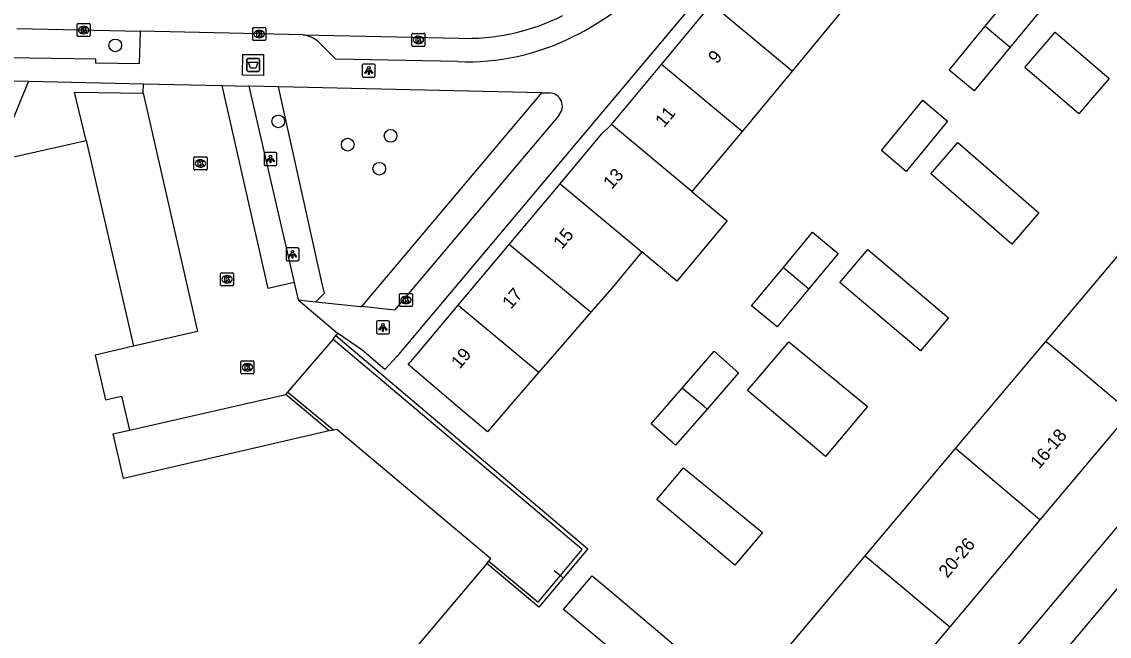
# Model space of a CAD drawing. Extents: x 162532 to 163264, y 381233 to 382042.
# Drawn here: x 162954.6 to 163038.2, y 381728.5 to 381775.7 of the extents above; entities that cross this region are included whole.
import ezdxf

# ---------------------------------------------------------------- set-up
doc = ezdxf.new("R2010")
doc.units = 0
for name, color, linetype in [('IMGEO_Afval_apart_plaats', 7, 'Continuous'), ('IMGEO_Boom', 7, 'Continuous'), ('IMGEO_Groenvoorziening', 7, 'Continuous'), ('IMGEO_Hek', 7, 'Continuous'), ('IMGEO_Kolk', 7, 'Continuous'), ('IMGEO_Lichtpunt', 7, 'Continuous'), ('IMGEO_Muur', 7, 'Continuous'), ('IMGEO_Pand', 7, 'Continuous'), ('IMGEO_Pand_nummerreeks', 7, 'Continuous'), ('IMGEO_Parkeervlak_open', 7, 'Continuous'), ('IMGEO_Rijbaan_lokaal_gesloten', 7, 'Continuous'), ('IMGEO_Rijbaan_lokaal_open', 7, 'Continuous'), ('IMGEO_Voetpad_gesloten', 7, 'Continuous'), ('IMGEO_Voetpad_open', 7, 'Continuous')]:
    doc.layers.add(name, color=color, linetype=linetype)

msp = doc.modelspace()

# ---------------------------------------------------------------- linework, layer by layer
at = {"layer": 'IMGEO_Afval_apart_plaats'}
for p, q in [((162971.93, 381771.991), (162971.93, 381772.791)), ((162971.93, 381772.791), (162971.93, 381771.991)), ((162972.03, 381772.891), (162972.82, 381772.891)), ((162972.82, 381772.891), (162972.03, 381772.891)), ((162972.92, 381772.791), (162972.92, 381771.991)), ((162972.92, 381771.991), (162972.92, 381772.791)), ((162972.82, 381771.891), (162972.03, 381771.891)), ((162972.03, 381771.891), (162972.82, 381771.891))]:
    msp.add_line(p, q, dxfattribs=at)
msp.add_lwpolyline([(162972.073, 381772.605), (162972.777, 381772.605), (162972.628, 381772.135), (162972.222, 381772.135), (162972.073, 381772.605)], dxfattribs=at)
for centre, start, end in [((162972.03, 381772.791), 90, 180), ((162972.03, 381772.791), 90, 180), ((162972.82, 381772.791), 0, 90), ((162972.82, 381772.791), 360, 90), ((162972.03, 381771.991), 180, 270), ((162972.03, 381771.991), 180, 270), ((162972.82, 381771.991), 270, 0), ((162972.82, 381771.991), 270, 0)]:
    msp.add_arc(centre, 0.1, start, end, dxfattribs=at)
at = {"layer": 'IMGEO_Boom'}
for centre in [(162961.829, 381773.885), (162974.352, 381768.05), (162982.984, 381766.94), (162979.697, 381766.265), (162982.114, 381764.415)]:
    msp.add_circle(centre, 0.489, dxfattribs=at)
at = {"layer": 'IMGEO_Groenvoorziening'}
for points in [[(162977.247, 381754.194), (162977.909, 381754.864), (162977.734, 381755.574), (162974.381, 381770.706)], [(162980.775, 381753.828), (162994.602, 381770.25)]]:
    msp.add_lwpolyline(points, dxfattribs=at)
at = {"layer": 'IMGEO_Hek'}
msp.add_lwpolyline([(162995.56, 381733.575), (162996.032, 381733.167)], dxfattribs=at)
at = {"layer": 'IMGEO_Kolk'}
for p, q in [((162958.909, 381774.634), (162958.909, 381775.486)), ((162958.984, 381775.56), (162959.836, 381775.56)), ((162959.397, 381775.34), (162959.422, 381775.34)), ((162959.91, 381775.486), (162959.91, 381774.634)), ((162972.391, 381774.327), (162972.391, 381775.179)), ((162972.466, 381775.253), (162973.318, 381775.253)), ((162973.392, 381775.179), (162973.392, 381774.327)), ((162959.836, 381774.56), (162958.984, 381774.56)), ((162959.42, 381774.78), (162959.395, 381774.78)), ((162972.902, 381774.473), (162972.877, 381774.473)), ((162972.879, 381775.033), (162972.904, 381775.033)), ((162984.621, 381773.886), (162984.621, 381774.738)), ((162984.696, 381774.812), (162985.548, 381774.812)), ((162985.109, 381774.592), (162985.134, 381774.592)), ((162985.622, 381774.738), (162985.622, 381773.886)), ((162973.318, 381774.253), (162972.466, 381774.253)), ((162985.548, 381773.812), (162984.696, 381773.812)), ((162985.132, 381774.032), (162985.107, 381774.032)), ((162967.881, 381764.392), (162967.881, 381765.244)), ((162967.956, 381765.318), (162968.808, 381765.318)), ((162968.882, 381765.244), (162968.882, 381764.392)), ((162968.808, 381764.318), (162967.956, 381764.318)), ((162968.392, 381764.538), (162968.367, 381764.538)), ((162968.369, 381765.098), (162968.394, 381765.098)), ((162969.921, 381755.504), (162969.921, 381756.356)), ((162969.996, 381756.43), (162970.848, 381756.43)), ((162970.409, 381756.21), (162970.434, 381756.21)), ((162970.922, 381756.356), (162970.922, 381755.504)), ((162970.848, 381755.43), (162969.996, 381755.43)), ((162970.432, 381755.65), (162970.407, 381755.65)), ((162983.664, 381753.912), (162983.664, 381754.764)), ((162983.739, 381754.838), (162984.591, 381754.838)), ((162984.152, 381754.618), (162984.177, 381754.618)), ((162984.665, 381754.764), (162984.665, 381753.912)), ((162984.591, 381753.838), (162983.739, 381753.838)), ((162984.175, 381754.058), (162984.15, 381754.058)), ((162971.489, 381748.736), (162971.489, 381749.588)), ((162971.564, 381749.662), (162972.416, 381749.662)), ((162971.977, 381749.442), (162972.002, 381749.442)), ((162972.49, 381749.588), (162972.49, 381748.736)), ((162972.416, 381748.662), (162971.564, 381748.662)), ((162972, 381748.882), (162971.975, 381748.882))]:
    msp.add_line(p, q, dxfattribs=at)
for points in [[(162958.909, 381774.634), (162958.909, 381775.486)], [(162958.984, 381775.56), (162959.836, 381775.56)], [(162959.23, 381775.26), (162959.353, 381775.26), (162959.353, 381775.109), (162959.483, 381775.26), (162959.647, 381775.26), (162959.501, 381775.109), (162959.654, 381774.86), (162959.502, 381774.86), (162959.417, 381775.024), (162959.353, 381774.957), (162959.353, 381774.86), (162959.23, 381774.86), (162959.23, 381775.26)], [(162959.91, 381775.486), (162959.91, 381774.634)], [(162972.391, 381774.327), (162972.391, 381775.179)], [(162972.466, 381775.253), (162973.318, 381775.253)], [(162973.392, 381775.179), (162973.392, 381774.327)], [(162959.836, 381774.56), (162958.984, 381774.56)], [(162972.712, 381774.953), (162972.835, 381774.953), (162972.835, 381774.802), (162972.965, 381774.953), (162973.129, 381774.953), (162972.983, 381774.802), (162973.136, 381774.553), (162972.984, 381774.553), (162972.899, 381774.717), (162972.835, 381774.65), (162972.835, 381774.553), (162972.712, 381774.553), (162972.712, 381774.953)], [(162984.621, 381773.886), (162984.621, 381774.738)], [(162984.696, 381774.812), (162985.548, 381774.812)], [(162984.942, 381774.512), (162985.065, 381774.512), (162985.065, 381774.361), (162985.195, 381774.512), (162985.359, 381774.512), (162985.213, 381774.361), (162985.366, 381774.112), (162985.214, 381774.112), (162985.129, 381774.276), (162985.065, 381774.209), (162985.065, 381774.112), (162984.942, 381774.112), (162984.942, 381774.512)], [(162985.622, 381774.738), (162985.622, 381773.886)], [(162973.318, 381774.253), (162972.466, 381774.253)], [(162985.548, 381773.812), (162984.696, 381773.812)], [(162967.881, 381764.392), (162967.881, 381765.244)], [(162967.956, 381765.318), (162968.808, 381765.318)], [(162968.882, 381765.244), (162968.882, 381764.392)], [(162968.808, 381764.318), (162967.956, 381764.318)], [(162968.202, 381765.018), (162968.325, 381765.018), (162968.325, 381764.867), (162968.455, 381765.018), (162968.619, 381765.018), (162968.473, 381764.867), (162968.626, 381764.618), (162968.474, 381764.618), (162968.389, 381764.782), (162968.325, 381764.715), (162968.325, 381764.618), (162968.202, 381764.618), (162968.202, 381765.018)], [(162969.921, 381755.504), (162969.921, 381756.356)], [(162969.996, 381756.43), (162970.848, 381756.43)], [(162970.242, 381756.13), (162970.365, 381756.13), (162970.365, 381755.979), (162970.495, 381756.13), (162970.659, 381756.13), (162970.513, 381755.979), (162970.666, 381755.73), (162970.514, 381755.73), (162970.429, 381755.894), (162970.365, 381755.827), (162970.365, 381755.73), (162970.242, 381755.73), (162970.242, 381756.13)], [(162970.922, 381756.356), (162970.922, 381755.504)], [(162970.848, 381755.43), (162969.996, 381755.43)], [(162983.664, 381753.912), (162983.664, 381754.764)], [(162983.739, 381754.838), (162984.591, 381754.838)], [(162983.985, 381754.538), (162984.108, 381754.538), (162984.108, 381754.387), (162984.238, 381754.538), (162984.402, 381754.538), (162984.256, 381754.387), (162984.409, 381754.138), (162984.257, 381754.138), (162984.172, 381754.302), (162984.108, 381754.235), (162984.108, 381754.138), (162983.985, 381754.138), (162983.985, 381754.538)], [(162984.665, 381754.764), (162984.665, 381753.912)], [(162984.591, 381753.838), (162983.739, 381753.838)], [(162971.489, 381748.736), (162971.489, 381749.588)], [(162971.564, 381749.662), (162972.416, 381749.662)], [(162971.81, 381749.362), (162971.933, 381749.362), (162971.933, 381749.211), (162972.063, 381749.362), (162972.227, 381749.362), (162972.081, 381749.211), (162972.234, 381748.962), (162972.082, 381748.962), (162971.997, 381749.126), (162971.933, 381749.059), (162971.933, 381748.962), (162971.81, 381748.962), (162971.81, 381749.362)], [(162972.49, 381749.588), (162972.49, 381748.736)], [(162972.416, 381748.662), (162971.564, 381748.662)]]:
    msp.add_lwpolyline(points, dxfattribs=at)
for centre, start, end in [((162958.986, 381775.484), 91.55205, 178.44795), ((162958.986, 381775.484), 91.55205, 178.44795), ((162959.834, 381775.484), 1.55205, 88.44795), ((162959.834, 381775.484), 1.55205, 88.44795), ((162972.468, 381775.177), 91.55205, 178.44795), ((162972.468, 381775.177), 91.55205, 178.44795), ((162973.316, 381775.177), 1.55205, 88.44795), ((162973.316, 381775.177), 1.55205, 88.44795), ((162958.986, 381774.636), 181.55205, 268.44795), ((162958.986, 381774.636), 181.55205, 268.44795), ((162959.834, 381774.636), 271.55205, 358.44795), ((162959.834, 381774.636), 271.55205, 358.44795), ((162972.468, 381774.329), 181.55205, 268.44795), ((162972.468, 381774.329), 181.55205, 268.44795), ((162973.316, 381774.329), 271.55205, 358.44795), ((162973.316, 381774.329), 271.55205, 358.44795), ((162984.698, 381774.736), 91.55205, 178.44795), ((162984.698, 381774.736), 91.55205, 178.44795), ((162985.546, 381774.736), 1.55205, 88.44795), ((162985.546, 381774.736), 1.55205, 88.44795), ((162984.698, 381773.888), 181.55205, 268.44795), ((162984.698, 381773.888), 181.55205, 268.44795), ((162985.546, 381773.888), 271.55205, 358.44795), ((162985.546, 381773.888), 271.55205, 358.44795), ((162967.958, 381765.242), 91.55205, 178.44795), ((162967.958, 381765.242), 91.55205, 178.44795), ((162968.806, 381765.242), 1.55205, 88.44795), ((162968.806, 381765.242), 1.55205, 88.44795), ((162967.958, 381764.394), 181.55205, 268.44795), ((162967.958, 381764.394), 181.55205, 268.44795), ((162968.806, 381764.394), 271.55205, 358.44795), ((162968.806, 381764.394), 271.55205, 358.44795), ((162969.998, 381756.354), 91.55205, 178.44795), ((162969.998, 381756.354), 91.55205, 178.44795), ((162970.846, 381756.354), 1.55205, 88.44795), ((162970.846, 381756.354), 1.55205, 88.44795), ((162969.998, 381755.506), 181.55205, 268.44795), ((162969.998, 381755.506), 181.55205, 268.44795), ((162970.846, 381755.506), 271.55205, 358.44795), ((162970.846, 381755.506), 271.55205, 358.44795), ((162983.741, 381754.762), 91.55205, 178.44795), ((162983.741, 381754.762), 91.55205, 178.44795), ((162984.589, 381754.762), 1.55205, 88.44795), ((162984.589, 381754.762), 1.55205, 88.44795), ((162983.741, 381753.914), 181.55205, 268.44795), ((162983.741, 381753.914), 181.55205, 268.44795), ((162984.589, 381753.914), 271.55205, 358.44795), ((162984.589, 381753.914), 271.55205, 358.44795), ((162971.566, 381749.586), 91.55205, 178.44795), ((162971.566, 381749.586), 91.55205, 178.44795), ((162972.414, 381749.586), 1.55205, 88.44795), ((162972.414, 381749.586), 1.55205, 88.44795), ((162971.566, 381748.738), 181.55205, 268.44795), ((162971.566, 381748.738), 181.55205, 268.44795), ((162972.414, 381748.738), 271.55205, 358.44795), ((162972.414, 381748.738), 271.55205, 358.44795)]:
    msp.add_arc(centre, 0.0765, start, end, dxfattribs=at)
for centre, major_axis, ratio, start_param, end_param in [((162959.396, 381775.06), (-0.387, 0.002), 0.722429, 4.712389, 7.853982), ((162959.421, 381775.06), (-0.39, 0.002), 0.717154, 1.570796, 4.712389), ((162972.878, 381774.753), (-0.387, 0.002), 0.722429, 4.712389, 7.853982), ((162972.903, 381774.753), (-0.39, 0.002), 0.717154, 1.570796, 4.712389), ((162985.108, 381774.312), (-0.387, 0.002), 0.722429, 4.712389, 7.853982), ((162985.133, 381774.312), (-0.39, 0.002), 0.717154, 1.570796, 4.712389), ((162968.368, 381764.818), (-0.387, 0.002), 0.722429, 4.712389, 7.853982), ((162968.393, 381764.818), (-0.39, 0.002), 0.717154, 1.570796, 4.712389), ((162970.408, 381755.93), (-0.387, 0.002), 0.722429, 4.712389, 7.853982), ((162970.433, 381755.93), (-0.39, 0.002), 0.717154, 1.570796, 4.712389), ((162984.151, 381754.338), (-0.387, 0.002), 0.722429, 4.712389, 7.853982), ((162984.176, 381754.338), (-0.39, 0.002), 0.717154, 1.570796, 4.712389), ((162971.976, 381749.162), (-0.387, 0.002), 0.722429, 4.712389, 7.853982), ((162972.001, 381749.162), (-0.39, 0.002), 0.717154, 1.570796, 4.712389)]:
    msp.add_ellipse(centre, major_axis=major_axis, ratio=ratio, start_param=start_param, end_param=end_param, dxfattribs=at)
at = {"layer": 'IMGEO_Lichtpunt'}
for p, q in [((162980.81, 381772.359), (162980.81, 381771.552)), ((162980.81, 381772.359), (162980.81, 381771.552)), ((162981.712, 381772.454), (162980.904, 381772.454)), ((162981.712, 381772.454), (162980.904, 381772.454)), ((162981.806, 381771.552), (162981.806, 381772.359)), ((162981.806, 381771.552), (162981.806, 381772.359)), ((162980.904, 381771.458), (162981.712, 381771.458)), ((162980.904, 381771.458), (162981.712, 381771.458)), ((162973.262, 381765.571), (162973.262, 381764.764)), ((162973.262, 381765.571), (162973.262, 381764.764)), ((162974.164, 381765.666), (162973.356, 381765.666)), ((162974.164, 381765.666), (162973.356, 381765.666)), ((162974.258, 381764.764), (162974.258, 381765.571)), ((162974.258, 381764.764), (162974.258, 381765.571)), ((162973.356, 381764.67), (162974.164, 381764.67)), ((162973.356, 381764.67), (162974.164, 381764.67)), ((162974.954, 381758.251), (162974.954, 381757.444)), ((162974.954, 381758.251), (162974.954, 381757.444)), ((162975.856, 381758.346), (162975.048, 381758.346)), ((162975.856, 381758.346), (162975.048, 381758.346)), ((162975.95, 381757.444), (162975.95, 381758.251)), ((162975.95, 381757.444), (162975.95, 381758.251)), ((162975.048, 381757.35), (162975.856, 381757.35)), ((162975.048, 381757.35), (162975.856, 381757.35)), ((162981.9, 381752.632), (162981.9, 381751.825)), ((162981.9, 381752.632), (162981.9, 381751.825)), ((162982.802, 381752.727), (162981.994, 381752.727)), ((162982.802, 381752.727), (162981.994, 381752.727)), ((162982.896, 381751.825), (162982.896, 381752.632)), ((162982.896, 381751.825), (162982.896, 381752.632)), ((162981.994, 381751.731), (162982.802, 381751.731)), ((162981.994, 381751.731), (162982.802, 381751.731))]:
    msp.add_line(p, q, dxfattribs=at)
for points in [[(162981.184, 381772.023), (162981.223, 381771.995), (162981.035, 381771.733), (162980.997, 381771.76), (162981.184, 381772.023)], [(162981.286, 381771.975), (162981.333, 381771.975), (162981.333, 381771.653), (162981.286, 381771.653), (162981.286, 381771.975)], [(162981.396, 381771.995), (162981.434, 381772.022), (162981.621, 381771.76), (162981.582, 381771.732), (162981.396, 381771.995)], [(162973.636, 381765.235), (162973.675, 381765.207), (162973.487, 381764.945), (162973.449, 381764.972), (162973.636, 381765.235)], [(162973.738, 381765.187), (162973.785, 381765.187), (162973.785, 381764.865), (162973.738, 381764.865), (162973.738, 381765.187)], [(162973.848, 381765.207), (162973.886, 381765.234), (162974.073, 381764.972), (162974.034, 381764.944), (162973.848, 381765.207)], [(162975.328, 381757.915), (162975.367, 381757.887), (162975.179, 381757.625), (162975.141, 381757.652), (162975.328, 381757.915)], [(162975.43, 381757.867), (162975.477, 381757.867), (162975.477, 381757.545), (162975.43, 381757.545), (162975.43, 381757.867)], [(162975.54, 381757.887), (162975.578, 381757.914), (162975.765, 381757.652), (162975.726, 381757.624), (162975.54, 381757.887)], [(162982.274, 381752.296), (162982.313, 381752.268), (162982.125, 381752.006), (162982.087, 381752.033), (162982.274, 381752.296)], [(162982.376, 381752.248), (162982.423, 381752.248), (162982.423, 381751.926), (162982.376, 381751.926), (162982.376, 381752.248)], [(162982.486, 381752.268), (162982.524, 381752.295), (162982.711, 381752.033), (162982.672, 381752.005), (162982.486, 381752.268)]]:
    msp.add_lwpolyline(points, dxfattribs=at)
for centre in [(162981.309, 381772.157), (162973.761, 381765.369), (162975.453, 381758.049), (162982.399, 381752.43)]:
    msp.add_circle(centre, 0.0994, dxfattribs=at)
for centre, start, end in [((162980.904, 381772.359), 90, 180), ((162980.904, 381772.359), 90, 180), ((162981.712, 381772.359), 0, 90), ((162981.712, 381772.359), 0, 90), ((162980.904, 381771.552), 180, 270), ((162980.904, 381771.552), 180, 270), ((162981.712, 381771.552), 270, 0), ((162981.712, 381771.552), 270, 360), ((162973.356, 381765.571), 90, 180), ((162973.356, 381765.571), 90, 180), ((162974.164, 381765.571), 0, 90), ((162974.164, 381765.571), 0, 90), ((162973.356, 381764.764), 180, 270), ((162973.356, 381764.764), 180, 270), ((162974.164, 381764.764), 270, 0), ((162974.164, 381764.764), 270, 360), ((162975.048, 381758.251), 90, 180), ((162975.048, 381758.251), 90, 180), ((162975.856, 381758.251), 0, 90), ((162975.856, 381758.251), 0, 90), ((162975.048, 381757.444), 180, 270), ((162975.048, 381757.444), 180, 270), ((162975.856, 381757.444), 270, 0), ((162975.856, 381757.444), 270, 360), ((162981.994, 381752.632), 90, 180), ((162981.994, 381752.632), 90, 180), ((162982.802, 381752.632), 0, 90), ((162982.802, 381752.632), 0, 90), ((162981.994, 381751.825), 180, 270), ((162981.994, 381751.825), 180, 270), ((162982.802, 381751.825), 270, 0), ((162982.802, 381751.825), 270, 360)]:
    msp.add_arc(centre, 0.0946, start, end, dxfattribs=at)
at = {"layer": 'IMGEO_Muur'}
for points in [[(162978.564, 381751.311), (162978.782, 381751.602)], [(162996.032, 381733.167), (162997.713, 381735.166), (162978.564, 381751.311)], [(162978.782, 381751.602), (162980.439, 381750.192), (162998.126, 381735.215), (162996.251, 381732.977)], [(162974.932, 381747.073), (162975.098, 381747.265)], [(162978.26, 381744.276), (162974.932, 381747.073)], [(162975.098, 381747.265), (162978.632, 381744.35)], [(162990.54, 381734.279), (162994.311, 381731.121), (162996.032, 381733.167)], [(162996.251, 381732.977), (162994.374, 381730.736), (162990.383, 381734.099)], [(162996.251, 381732.977), (162996.032, 381733.167)]]:
    msp.add_lwpolyline(points, dxfattribs=at)
at = {"layer": 'IMGEO_Pand'}
for points in [[(163028.667, 381775.357), (163030.943, 381778.121), (163032.879, 381776.527), (163030.595, 381773.754)], [(163003.798, 381772.423), (163007.641, 381777.046)], [(163013.825, 381771.906), (163007.641, 381777.046)], [(163017.739, 381776.615), (163013.825, 381771.906)], [(163030.595, 381773.754), (163027.823, 381770.388), (163025.887, 381771.982), (163028.667, 381775.357)], [(163028.667, 381775.357), (163030.595, 381773.754)], [(163031.705, 381772.192), (163034.036, 381774.911), (163038.195, 381771.347), (163036.917, 381769.856), (163035.864, 381768.628), (163031.705, 381772.192)], [(162999.951, 381767.805), (163003.798, 381772.423)], [(163009.983, 381767.283), (163003.798, 381772.423)], [(163013.825, 381771.906), (163009.983, 381767.283)], [(163020.704, 381765.817), (163023.882, 381769.682), (163025.772, 381768.071), (163022.948, 381764.636), (163022.595, 381764.206), (163020.704, 381765.817)], [(162996.004, 381763.255), (162999.199, 381767.057), (162999.951, 381767.805)], [(163006.14, 381762.66), (162999.951, 381767.805)], [(163009.983, 381767.283), (163006.14, 381762.66)], [(162952.644, 381765.024), (162959.605, 381766.586)], [(162959.605, 381766.586), (162963.235, 381750.796)], [(163024.485, 381764.023), (163026.565, 381766.421), (163032.793, 381761.02), (163030.714, 381758.622), (163024.485, 381764.023)], [(162992.092, 381758.6), (162996.004, 381763.255)], [(162996.004, 381763.255), (163000, 381759.933), (163002.291, 381758.029)], [(163006.14, 381762.66), (163008.832, 381760.423), (163004.983, 381755.792), (163002.291, 381758.029)], [(163013.16, 381756.835), (163015.41, 381759.542), (163017.376, 381757.909), (163015.125, 381755.201)], [(163033.321, 381751.159), (163040.254, 381759.391)], [(162988.18, 381753.945), (162992.092, 381758.6)], [(162998.362, 381753.389), (162998.159, 381753.558), (162992.092, 381758.6)], [(163002.291, 381758.029), (163000, 381755.273), (162998.362, 381753.389)], [(163017.497, 381755.685), (163019.657, 381758.225), (163025.847, 381752.964), (163023.687, 381750.424), (163017.497, 381755.685)], [(163015.125, 381755.201), (163012.684, 381752.264), (163010.718, 381753.897), (163013.16, 381756.835)], [(163013.16, 381756.835), (163015.125, 381755.201)], [(162994.372, 381748.798), (162992.373, 381746.497), (162990.436, 381744.206), (162988.151, 381746.141), (162984.336, 381749.372), (162984.864, 381750), (162988.18, 381753.945)], [(162988.18, 381753.945), (162992.926, 381750), (162994.372, 381748.798)], [(162998.362, 381753.389), (162995.417, 381750), (162994.372, 381748.798)], [(163010.411, 381747.373), (163013.576, 381751.122), (163019.63, 381746.169), (163016.388, 381742.328), (163010.411, 381747.373)], [(163026.388, 381742.927), (163032.345, 381750), (163033.321, 381751.159)], [(163039.799, 381745.703), (163034.697, 381750), (163033.321, 381751.159)], [(162963.235, 381750.796), (162960.289, 381750.111), (162961.075, 381746.66), (162962.324, 381746.962), (162962.923, 381744.34)], [(163005.383, 381747.554), (163007.853, 381750.397), (163009.529, 381748.908), (163009.712, 381748.746), (163007.295, 381745.965)], [(163007.295, 381745.965), (163004.881, 381743.187), (163004.634, 381743.401), (163003.004, 381744.817), (163005.383, 381747.554)], [(163007.295, 381745.965), (163007.075, 381746.148), (163005.383, 381747.554)], [(163039.799, 381745.703), (163032.871, 381737.466)], [(162978.26, 381744.276), (162962.475, 381740.62), (162961.679, 381744.052), (162962.923, 381744.34)], [(162978.632, 381744.35), (162978.26, 381744.276)], [(162990.54, 381734.279), (162990.686, 381734.457), (162978.865, 381744.381), (162978.632, 381744.35)], [(163019.454, 381734.695), (163026.388, 381742.927)], [(163032.871, 381737.466), (163026.388, 381742.927)], [(163011.548, 381736.493), (163009.426, 381733.979), (163003.449, 381739.023), (163005.494, 381741.446), (163011.548, 381736.493)], [(163032.871, 381737.466), (163025.944, 381729.23)], [(162990.383, 381734.099), (162990.54, 381734.279)], [(163012.521, 381726.464), (163019.454, 381734.695)], [(163019.454, 381734.695), (163025.944, 381729.23)], [(162990.383, 381734.099), (162964.729, 381703.699)], [(163004.682, 381727.897), (163002.511, 381725.334), (163000, 381727.439), (162996.266, 381730.57), (162998.463, 381733.165), (163000, 381731.863), (163004.682, 381727.897)], [(163025.944, 381729.23), (163019.017, 381720.994)]]:
    msp.add_lwpolyline(points, dxfattribs=at)
at = {"layer": 'IMGEO_Parkeervlak_open'}
for points in [[(162959.605, 381766.586), (162958.709, 381770.287), (162963.978, 381770.228)], [(162972.1, 381770.758), (162975.572, 381755.68)]]:
    msp.add_lwpolyline(points, dxfattribs=at)
at = {"layer": 'IMGEO_Rijbaan_lokaal_gesloten'}
msp.add_lwpolyline([(162975.098, 381747.265), (162978.564, 381751.311)], dxfattribs=at)
at = {"layer": 'IMGEO_Rijbaan_lokaal_open'}
for points in [[(162954.27, 381775.179), (162963.739, 381774.97)], [(162976.265, 381774.685), (162963.739, 381774.97)], [(162976.265, 381774.685), (162988.222, 381774.437)], [(162963.978, 381770.228), (162968.146, 381751.914), (162963.235, 381750.796)], [(162963.978, 381770.228), (162963.993, 381770.94)], [(162963.993, 381770.94), (162970.047, 381770.804)], [(162975.572, 381755.68), (162973.591, 381755.23), (162970.047, 381770.804)], [(162975.572, 381755.68), (162975.881, 381754.336)], [(162975.881, 381754.336), (162978.902, 381751.794)], [(162978.902, 381751.794), (162978.782, 381751.602)], [(162962.923, 381744.34), (162974.932, 381747.073)], [(163050.901, 381746.533), (163013.536, 381702.12)]]:
    msp.add_lwpolyline(points, dxfattribs=at)
msp.add_arc((162988.835, 381790.903), 16.478, 267.86696, 296.61021, dxfattribs=at)
at = {"layer": 'IMGEO_Voetpad_gesloten'}
msp.add_lwpolyline([(162973.234, 381773.187), (162973.222, 381771.586), (162971.617, 381771.593), (162971.625, 381773.196), (162973.234, 381773.187)], dxfattribs=at)
at = {"layer": 'IMGEO_Voetpad_open'}
for points in [[(163019.982, 381792.725), (163019.638, 381793.018), (163018.451, 381791.621), (162983.456, 381749.996), (162982.545, 381748.989), (162980.782, 381750.497), (162978.902, 381751.794)], [(162963.739, 381774.97), (162963.678, 381772.461), (162960.334, 381772.509), (162960.338, 381772.817), (162950.071, 381772.984), (162950.05, 381772.687), (162947.619, 381772.518), (162947.568, 381772.829)], [(162988.154, 381772.638), (162978.779, 381772.823), (162977.437, 381774.156)], [(162955.177, 381771.139), (162952.644, 381765.024)], [(162953.038, 381771.187), (162955.177, 381771.139)], [(162955.177, 381771.139), (162963.993, 381770.94)], [(162970.047, 381770.804), (162972.1, 381770.758)], [(162974.381, 381770.706), (162972.1, 381770.758)], [(162994.602, 381770.25), (162974.381, 381770.706)], [(162994.602, 381770.25), (162995.182, 381770.237)], [(162995.902, 381768.514), (162983.293, 381753.567), (162980.775, 381753.828)], [(162988.098, 381676.598), (163000, 381690.752), (163049.821, 381750), (163057.405, 381759.019), (163056.336, 381759.96), (163057.544, 381761.374)], [(162975.881, 381754.336), (162977.247, 381754.194)], [(162977.247, 381754.194), (162980.67, 381753.839), (162980.751, 381753.831), (162980.775, 381753.828)]]:
    msp.add_lwpolyline(points, dxfattribs=at)
for centre, radius, start, end in [((162987.039, 381794.594), 22.381, 296.47792, 316.47756), ((162976.035, 381772.612), 2.085, 47.74921, 83.66527), ((162988.837, 381790.89), 18.265, 267.85798, 296.61038), ((162995.161, 381769.216), 1.021, 316.53296, 88.82478)]:
    msp.add_arc(centre, radius, start, end, dxfattribs=at)

# ---------------------------------------------------------------- texts
at = {"layer": 'IMGEO_Pand_nummerreeks'}
for s, rotation, p in [('9', 50.26348, (163008.055, 381772.412)), ('11', 50.26348, (163003.992, 381767.525)), ('13', 48.45175, (162999.969, 381762.785)), ('15', 49.57981, (162996.147, 381758.18)), ('17', 49.57981, (162992.231, 381753.582)), ('19', 49.95006, (162988.297, 381748.986)), ('16-18', 49.93338, (163032.803, 381741.3)), ('20-26', 49.93403, (163025.756, 381732.922))]:
    msp.add_text(s, height=1, rotation=rotation, dxfattribs=at).set_placement(p)

doc.saveas('drawing.dxf')
